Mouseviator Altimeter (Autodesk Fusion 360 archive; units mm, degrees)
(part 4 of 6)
sketch "Back Outline" plane through (0, 39, 0) normal (0, 1, 0) x axis (-1, 0, 0)
  line L1 (14.9023, 9.8465) -> (12.6303, 7.5745)
  line L2 (18.0511, 2.3887) -> (20.2056, 4.5432)
  line L3 (17.6976, 2.7423) -> (18.0511, 2.3887)
  line L4 (19.852, 4.8967) -> (17.6976, 2.7423)
  line L5 (12.9839, 7.2209) -> (15.2558, 9.4929)
  line L6 (12.6303, 7.5745) -> (12.9839, 7.2209)
  line L7 (-2.5507, -17.506) -> (-4.8967, -19.852)
  line L8 (-2.1971, -17.8596) -> (-2.5507, -17.506)
  line L9 (-4.5432, -20.2056) -> (-2.1971, -17.8596)
  line L10 (-7.6598, -12.7156) -> (-9.8465, -14.9023)
  line L11 (-7.3063, -13.0692) -> (-7.6598, -12.7156)
  line L12 (-9.4929, -15.2558) -> (-7.3063, -13.0692)
  line L13 (-41.4655, -13.9983) -> (-36.1766, -13.9983)
  line L14 (-41.4655, -20.5361) -> (-41.4655, -13.9983)
  line L15 (-36.4994, -34.1766) -> (-41.1157, -22.3885)
  line L16 (-23.2139, -41.1177) -> (-33.6166, -37.0564)
  curve K1 (-21.3665, -41.4655) -> (-21.9088, -41.4365)
  line L17 (28.9018, -41.4655) -> (-21.3665, -41.4655)
  line L18 (41.4655, 20.5361) -> (41.4655, -28.9018)
  curve K2 (41.4365, 21.0784) -> (41.4655, 20.5361)
  line L19 (36.4994, 34.1766) -> (41.1157, 22.3885)
  line L20 (26.5185, 40.8706) -> (34.1546, 36.8093)
  line L21 (14.9161, 41.4655) -> (24.1331, 41.4655)
  line L22 (14.9161, 35.8845) -> (14.9161, 41.4655)
  line L23 (-3.0839, 41.4655) -> (-3.0839, 35.8845)
  line L24 (-24.1231, 41.4655) -> (-3.0839, 41.4655)
  line L25 (-33.6166, 37.0564) -> (-26.5251, 40.8618)
  line L26 (-41.1157, 22.3885) -> (-36.4994, 34.1766)
  line L27 (-41.4655, 4.0017) -> (-41.4655, 20.5361)
  line L28 (-36.1766, 4.0017) -> (-41.4655, 4.0017)
  line L29 (0, -31.4655) -> (0, 0)
  line L30 (-3.75, -18.1203) -> (-3.75, -31.4655)
  line L31 (3.75, -31.4655) -> (3.75, -0.2296)
  line L32 (0, 0) -> (30.9023, -30.9023)
  line L33 (-2.6517, -2.6517) -> (28.2507, -33.554)
  line L34 (2.6517, 2.6517) -> (33.554, -28.2507)
  line L35 (30.3606, 27.5008) -> (31.4655, 19.6071)
  line L36 (-20.4401, -31.4655) -> (-27.6044, -29.4666)
  line L37 (-22.8865, 31.4655) -> (-17.677, 31.4655)
  line L38 (-27.8686, 28.7921) -> (-22.8865, 31.4655)
  line L39 (-31.4655, 19.6071) -> (-27.8686, 28.7921)
  line L40 (-31.4655, 18.6813) -> (-31.4655, 19.6071)
  line L41 (30.4699, 22.1494) -> (31.4655, 19.6071)
  line L42 (-20.4401, -31.4655) -> (-25.1073, -29.6434)
  line L43 (28.9018, -31.4655) -> (-20.4401, -31.4655)
  line L44 (31.4655, 19.6071) -> (31.4655, -28.9018)
  arc A1 centre (17.5539, 7.1948) radius 3.75 clockwise from (14.9023, 9.8465) to (20.2056, 4.5432)
  arc A2 centre (17.5539, 7.1948) radius 3.25 clockwise from (15.2558, 9.4929) to (19.852, 4.8967)
  arc A3 centre (-7.1948, -17.5539) radius 3.75 clockwise from (-4.5432, -20.2056) to (-9.8465, -14.9023)
  arc A4 centre (-7.1948, -17.5539) radius 3.25 clockwise from (-4.8967, -19.852) to (-9.4929, -15.2558)
  arc A5 centre (-36.3855, -20.5361) radius 5.08 clockwise from (-41.1157, -22.3885) to (-41.4655, -20.5361)
  arc A6 centre (-31.7692, -32.3242) radius 5.08 clockwise from (-33.6166, -37.0564) to (-36.4994, -34.1766)
  arc A7 centre (-21.3665, -36.3855) radius 5.08 clockwise from (-21.9088, -41.4365) to (-23.2139, -41.1177)
  arc A8 centre (28.9018, -28.9018) radius 12.5637 clockwise from (41.4655, -28.9018) to (28.9018, -41.4655)
  arc A9 centre (36.3855, 20.5361) radius 5.08 clockwise from (41.1157, 22.3885) to (41.4365, 21.0784)
  arc A10 centre (31.7692, 32.3242) radius 5.08 clockwise from (34.1546, 36.8093) to (36.4994, 34.1766)
  arc A11 centre (24.1331, 36.3855) radius 5.08 clockwise from (24.1331, 41.4655) to (26.5185, 40.8706)
  arc A12 centre (5.9161, 24.325) radius 14.65 clockwise from (14.9161, 35.8845) to (-3.0839, 35.8845)
  arc A13 centre (-24.1231, 36.3855) radius 5.08 clockwise from (-26.5251, 40.8618) to (-24.1231, 41.4655)
  arc A14 centre (-31.7692, 32.3242) radius 5.08 clockwise from (-36.4994, 34.1766) to (-33.6166, 37.0564)
  arc A15 centre (-36.3855, 20.5361) radius 5.08 clockwise from (-41.4655, 20.5361) to (-41.1157, 22.3885)
  arc A16 centre (-24.6171, -4.9983) radius 14.65 clockwise from (-36.1766, 4.0017) to (-36.1766, -13.9983)
  circle C1 centre (17.5539, 7.1948) radius 1.4
  circle C2 centre (-7.1948, -17.5539) radius 1.4
  circle C3 centre (30.9023, -30.9023) radius 5.5
  circle C4 centre (-18.76, 36.96) radius 1
  circle C5 centre (31.4309, 31.4309) radius 2.159
  circle C6 centre (-31.4309, -31.4309) radius 2.159
  circle C7 centre (-18.76, -36.96) radius 1
  circle C8 centre (18.76, 36.96) radius 1
  circle C9 centre (-31.4309, 31.4309) radius 2.159
  circle C10 centre (0, 0) radius 5
  circle C11 centre (-36.96, 18.76) radius 1
  circle C12 centre (36.96, 18.76) radius 1
  circle C13 centre (-36.96, -18.76) radius 1
  circle C14 centre (0, 0) radius 22.5
  circle C15 centre (30.9023, -30.9023) radius 15
  arc A17 centre (5.9161, 24.325) radius 24.65 clockwise from (-18.101, 18.7749) to (-17.677, 31.4655)
  arc A18 centre (-24.6171, -4.9983) radius 24.65 clockwise from (-31.4655, 18.6813) to (-18.101, 18.7749)
  arc A19 centre (5.9161, 24.325) radius 24.65 clockwise from (30.4699, 22.1494) to (-0.6001, 0.5519)
  arc A20 centre (-24.6171, -4.9983) radius 24.65 clockwise from (-0.6001, 0.5519) to (-25.1073, -29.6434)
  arc A21 centre (28.9018, -28.9018) radius 2.5637 clockwise from (31.4655, -28.9018) to (28.9018, -31.4655)
  point P1 (0, 0)
  point P86 (0, 0)
  point P87 (0, -31.4655)
  point P88 (-3.75, -31.4655)
  point P89 (-3.75, -18.1203)
  point P90 (3.75, -0.2296)
  point P91 (3.75, -31.4655)
  point P92 (0, 0)
  point P62 (30.9023, -30.9023)
  point P93 (30.9023, -30.9023)
  point P94 (0, 0)
  point P99 (30.9023, -30.9023)
  coincident P1 P86
  coincident P87 L43
  perpendicular L29 L43
  coincident P88 L43
  coincident P89 A20
  vertical L30
  coincident P90 A19
  coincident P91 L43
  perpendicular L31 L43
  coincident P1 P92
  coincident P62 P93
  coincident P1 P94
  coincident P93 P99
  dimension "d336" = -10
  dimension "d337" distance L29 L30 = 3.75 (= "( 7.5 / 2 ) * 1 mm")
  dimension "d338" distance L29 L31 = 3.75 (= "d337")
  dimension "d339" diameter C14 = 45
  dimension "d340" = -3.75 (= "( -7.5 / 2 ) * 1 mm")
  dimension "d341" = 3.75 (= "( 7.5 / 2 ) * 1 mm")
  dimension "d344" diameter C15 = 30
extrude "Extrude13" cut sketch "Back Outline" profile of A1 A19 L43 A20 L44 C14 L33 L34 C15 L35 L36 to an object
fillet "Fillet2" radius 1.5
sketch "Support Holes" plane through (0, 3.5, 0) normal (0, -1, 0) x axis (1, 0, 0)
  line L1 (32.6235, 7.6129) -> (25.3452, 5.7982)
  line L2 (25.3452, -5.7982) -> (32.6737, -7.3944)
  curve K1 (-41.4655, 20.5361) -> (-41.4365, 21.0784)
  line L3 (-41.4655, -28.9018) -> (-41.4655, 20.5361)
  line L4 (21.3665, -41.4655) -> (-28.9018, -41.4655)
  curve K2 (21.9088, -41.4365) -> (21.3665, -41.4655)
  line L5 (33.6166, -37.0564) -> (23.2139, -41.1177)
  line L6 (41.1157, -22.3885) -> (36.4994, -34.1766)
  line L7 (41.4655, 20.5361) -> (41.4655, -20.5361)
  line L8 (36.4994, 34.1766) -> (41.1157, 22.3885)
  line L9 (26.5251, 40.8618) -> (33.6166, 37.0564)
  line L10 (-24.1331, 41.4655) -> (24.1231, 41.4655)
  line L11 (-34.1546, 36.8093) -> (-26.5185, 40.8706)
  line L12 (-41.1157, 22.3885) -> (-36.4994, 34.1766)
  circle C1 centre (-30.9024, -30.9024) radius 3.25
  circle C2 centre (-0.2224, 0.034) radius 5.25
  circle C3 centre (18.76, 36.96) radius 1.4
  circle C4 centre (-36.96, 18.76) radius 1.4
  circle C5 centre (-18.76, 36.96) radius 1.4
  circle C6 centre (36.96, -18.76) radius 1.4
  circle C7 centre (31.4309, 31.4309) radius 2.159
  circle C8 centre (36.96, 18.76) radius 1.4
  circle C9 centre (18.76, -36.96) radius 1.4
  circle C10 centre (-31.4309, 31.4309) radius 2.159
  arc A1 centre (0, 0) radius 33.5 clockwise from (32.6235, 7.6129) to (32.6737, -7.3944)
  arc A2 centre (0, 0) radius 26 clockwise from (25.3452, 5.7982) to (25.3452, -5.7982)
  circle C11 centre (31.4309, -31.4309) radius 2.159
  arc A3 centre (-36.3855, 20.5361) radius 5.08 clockwise from (-41.4365, 21.0784) to (-41.1157, 22.3885)
  arc A4 centre (-28.9018, -28.9018) radius 12.5637 clockwise from (-28.9018, -41.4655) to (-41.4655, -28.9018)
  arc A5 centre (21.3665, -36.3855) radius 5.08 clockwise from (23.2139, -41.1177) to (21.9088, -41.4365)
  arc A6 centre (31.7692, -32.3242) radius 5.08 clockwise from (36.4994, -34.1766) to (33.6166, -37.0564)
  arc A7 centre (36.3855, -20.5361) radius 5.08 clockwise from (41.4655, -20.5361) to (41.1157, -22.3885)
  arc A8 centre (36.3855, 20.5361) radius 5.08 clockwise from (41.1157, 22.3885) to (41.4655, 20.5361)
  arc A9 centre (31.7692, 32.3242) radius 5.08 clockwise from (33.6166, 37.0564) to (36.4994, 34.1766)
  arc A10 centre (24.1231, 36.3855) radius 5.08 clockwise from (24.1231, 41.4655) to (26.5251, 40.8618)
  arc A11 centre (-24.1331, 36.3855) radius 5.08 clockwise from (-26.5185, 40.8706) to (-24.1331, 41.4655)
  arc A12 centre (-31.7692, 32.3242) radius 5.08 clockwise from (-36.4994, 34.1766) to (-34.1546, 36.8093)
  circle C12 centre (-17.3319, -36.9825) radius 1
  circle C13 centre (-37.3525, -16.6048) radius 1
extrude "Extrude6" cut sketch "Support Holes" profile of C12 C13 to an object
hole "Hole2" HoleDepth 4 HoleDiameter 5 TipAngle 180
extrude "Extrude3" cut sketch "Sketch1" to an object
decal "Decal2"
extrude "Extrude5" cut sketch "Sketch1" profile of A12 A14 L16 A17 A18 L20 to an object
work_plane "WorkPlane2" AlongDistance 0.75
sketch "Sketch1" plane through (0, 8.25, 0) normal (0, 1, 0) x axis (1, 0, 0)
  line L1 (38.0143, -15.1613) -> (35.9057, -22.3587)
  line L2 (19.7873, -9.8212) -> (38.0143, -15.1613)
  line L3 (17.6786, -17.0187) -> (19.7873, -9.8212)
  line L4 (35.9057, -22.3587) -> (17.6786, -17.0187)
  line L5 (23.336, -34.9394) -> (14.184, -38.9806)
  line L6 (15.0207, -16.1078) -> (23.336, -34.9394)
  line L7 (5.8687, -20.149) -> (15.0207, -16.1078)
  line L8 (14.184, -38.9806) -> (5.8687, -20.149)
  line L9 (22.1039, 35.2627) -> (15.4161, 38.6573)
  line L10 (16.8157, 24.8442) -> (22.1039, 35.2627)
  line L11 (10.1279, 28.2387) -> (16.8157, 24.8442)
  line L12 (15.4161, 38.6573) -> (10.1279, 28.2387)
  line L13 (35.2627, 22.1039) -> (38.6573, 15.4161)
  line L14 (24.8442, 16.8157) -> (35.2627, 22.1039)
  line L15 (28.2387, 10.1279) -> (24.8442, 16.8157)
  line L16 (38.6573, 15.4161) -> (28.2387, 10.1279)
  line L17 (-35.8292, 20.0315) -> (-38.8758, 13.1782)
  line L18 (-25.675, 15.5175) -> (-35.8292, 20.0315)
  line L19 (-28.7216, 8.6642) -> (-25.675, 15.5175)
  line L20 (-38.8758, 13.1782) -> (-28.7216, 8.6642)
  line L21 (-13.9363, 38.5738) -> (-20.7275, 35.3911)
  line L22 (-9.2354, 28.5431) -> (-13.9363, 38.5738)
  line L23 (-16.0266, 25.3604) -> (-9.2354, 28.5431)
  line L24 (-20.7275, 35.3911) -> (-16.0266, 25.3604)
  circle C1 centre (0, 0) radius 30
  circle C2 centre (36.96, 18.76) radius 3.75
  circle C3 centre (36.96, -18.76) radius 3.75
  circle C4 centre (18.76, 36.96) radius 3.75
  circle C5 centre (-37.3525, 16.6048) radius 3.75
  circle C6 centre (-17.3319, 36.9825) radius 3.75
  circle C7 centre (18.76, -36.96) radius 3.75
  point P1 (0, 0)
  point P2 (0, 0)
  point P3 (35.9057, -22.3587)
  point P4 (38.0143, -15.1613)
  point P18 (36.96, -18.76)
  point P19 (18.76, -36.96)
  point P39 (18.76, -36.96)
  point P16 (36.96, -18.76)
  point P15 (36.96, 18.76)
  point P20 (36.96, 18.76)
  point P21 (18.76, 36.96)
  point P14 (10.1279, 28.2387)
  point P13 (16.8157, 24.8442)
  point P12 (22.1039, 35.2627)
  point P17 (18.76, 36.96)
  point P25 (28.2387, 10.1279)
  point P24 (24.8442, 16.8157)
  point P22 (38.6573, 15.4161)
  point P23 (35.2627, 22.1039)
  point P26 (36.96, 18.76)
  point P30 (-35.8292, 20.0315)
  point P29 (-38.8758, 13.1782)
  point P34 (-13.9363, 38.5738)
  point P33 (-20.7275, 35.3911)
  point P37 (-17.3319, 36.9825)
  point P28 (-17.3319, 36.9825)
  point P35 (-9.2354, 28.5431)
  point P36 (-16.0266, 25.3604)
  point P38 (-37.3525, 16.6048)
  point P32 (-28.7216, 8.6642)
  point P31 (-25.675, 15.5175)
  point P27 (-37.3525, 16.6048)
  coincident P1 P2
  perpendicular L1 L2
  parallel L1 L3
  parallel L2 L4
  perpendicular L5 L6
  parallel L5 L7
  parallel L6 L8
  perpendicular L9 L10
  parallel L9 L11
  parallel L10 L12
  coincident P3 C3
  coincident P4 C3
  midpoint L1 P18
  midpoint L5 P19
  coincident P19 P39
  coincident P16 P18
  coincident P15 P20
  midpoint L9 P21
  coincident C1 P14
  coincident C1 P13
  coincident P12 C4
  coincident P17 P21
  perpendicular L13 L14
  parallel L13 L15
  parallel L14 L16
  coincident C1 P25
  coincident C1 P24
  coincident C2 P22
  coincident C2 P23
  midpoint L13 P26
  perpendicular L17 L18
  parallel L17 L19
  parallel L18 L20
  coincident C5 P30
  coincident C5 P29
  perpendicular L21 L22
  parallel L21 L23
  parallel L22 L24
  coincident C6 P34
  coincident C6 P33
  midpoint L21 P37
  coincident P28 P37
  coincident C1 P35
  coincident C1 P36
  midpoint L17 P38
  coincident C1 P32
  coincident C1 P31
  coincident P27 P38
  dimension "d270" diameter C1 = 60
extrude "Extrude1" new body sketch "Sketch1" profile of C1 C2 L14 L16 C6 L22 L24 along normal blind 5
chamfer "Chamfer1" distance 11 distance 4
fillet "Fillet1" radius 1.5 0.5
mirror "Mirror1" mirrorStitchTolerance 0.1
as_built_joint "As-built3" OffsetX 0 OffsetY 0 OffsetZ 0 AngleZ 0
as_built_joint "As-built5" OffsetX 0 OffsetY 0 OffsetZ 0 AngleZ 0 RotateRest -50
as_built_joint "As-built6"
as_built_joint "As-built7" OffsetX 0 OffsetY 0 OffsetZ 0 AngleZ 0
as_built_joint "As-built8" OffsetX 0 OffsetY 0 OffsetZ 0 AngleZ 0
motion_link "MotionLink1" Value1 360 Value2 -360
motion_link "MotionLink2" Value1 360 Value2 -360
sketch "D Shaft" plane through (0, 18.05, 0) normal (0, -1, 0) x axis (1, 0, 0)
  line L1 (-4.5346, -8.7261) -> (-4.7021, -8.8256)
  line L2 (-4.3651, -8.6158) -> (-4.5346, -8.7261)
  line L3 (-4.2116, -8.5065) -> (-4.3651, -8.6158)
  line L4 (-4.0743, -8.3999) -> (-4.2116, -8.5065)
  line L5 (-3.9541, -8.2982) -> (-4.0743, -8.3999)
  line L6 (-3.8486, -8.201) -> (-3.9541, -8.2982)
  line L7 (-3.7582, -8.1106) -> (-3.8486, -8.201)
  line L8 (-3.681, -8.0265) -> (-3.7582, -8.1106)
  line L9 (-3.6174, -7.9512) -> (-3.681, -8.0265)
  line L10 (-3.566, -7.8849) -> (-3.6174, -7.9512)
  line L11 (-3.4961, -7.7827) -> (-3.566, -7.8849)
  line L12 (-3.4639, -7.7262) -> (-3.4961, -7.7827)
  line L13 (-3.4053, -7.6041) -> (-3.4639, -7.7262)
  line L14 (-3.3474, -7.5073) -> (-3.4053, -7.6041)
  line L15 (-3.288, -7.4286) -> (-3.3474, -7.5073)
  line L16 (-3.2286, -7.3679) -> (-3.288, -7.4286)
  line L17 (-3.1993, -7.3443) -> (-3.2286, -7.3679)
  line L18 (-3.1705, -7.3251) -> (-3.1993, -7.3443)
  line L19 (-3.1424, -7.3103) -> (-3.1705, -7.3251)
  line L20 (-3.1151, -7.2999) -> (-3.1424, -7.3103)
  line L21 (-3.0889, -7.2938) -> (-3.1151, -7.2999)
  line L22 (-3.0638, -7.292) -> (-3.0889, -7.2938)
  line L23 (-3.0401, -7.2944) -> (-3.0638, -7.292)
  line L24 (-3.0179, -7.301) -> (-3.0401, -7.2944)
  line L25 (-2.8761, -7.358) -> (-3.0179, -7.301)
  line L26 (-2.702, -7.4237) -> (-2.8761, -7.358)
  line L27 (-2.5264, -7.4853) -> (-2.702, -7.4237)
  line L28 (-2.3811, -7.5327) -> (-2.5264, -7.4853)
  line L29 (-2.3599, -7.542) -> (-2.3811, -7.5327)
  line L30 (-2.3402, -7.5554) -> (-2.3599, -7.542)
  line L31 (-2.3221, -7.5729) -> (-2.3402, -7.5554)
  line L32 (-2.306, -7.5944) -> (-2.3221, -7.5729)
  line L33 (-2.2918, -7.6199) -> (-2.306, -7.5944)
  line L34 (-2.2797, -7.6493) -> (-2.2918, -7.6199)
  line L35 (-2.27, -7.6825) -> (-2.2797, -7.6493)
  line L36 (-2.2627, -7.7195) -> (-2.27, -7.6825)
  line L37 (-2.2562, -7.8041) -> (-2.2627, -7.7195)
  line L38 (-2.2613, -7.9026) -> (-2.2562, -7.8041)
  line L39 (-2.2792, -8.014) -> (-2.2613, -7.9026)
  line L40 (-2.3128, -8.1452) -> (-2.2792, -8.014)
  line L41 (-2.3244, -8.2092) -> (-2.3128, -8.1452)
  line L42 (-2.3366, -8.3324) -> (-2.3244, -8.2092)
  line L43 (-2.3398, -8.4162) -> (-2.3366, -8.3324)
  line L44 (-2.3395, -8.5148) -> (-2.3398, -8.4162)
  line L45 (-2.3344, -8.6288) -> (-2.3395, -8.5148)
  line L46 (-2.3233, -8.7562) -> (-2.3344, -8.6288)
  line L47 (-2.3049, -8.8985) -> (-2.3233, -8.7562)
  line L48 (-2.2782, -9.0536) -> (-2.3049, -8.8985)
  line L49 (-2.2416, -9.2235) -> (-2.2782, -9.0536)
  line L50 (-2.1943, -9.4059) -> (-2.2416, -9.2235)
  line L51 (-2.1353, -9.5994) -> (-2.1943, -9.4059)
  line L52 (-2.071, -9.7833) -> (-2.1353, -9.5994)
  line L53 (-1.2767, -9.7508) -> (-1.4, -9.9016)
  line L54 (-1.1551, -9.5891) -> (-1.2767, -9.7508)
  line L55 (-1.0482, -9.434) -> (-1.1551, -9.5891)
  line L56 (-0.9557, -9.2868) -> (-1.0482, -9.434)
  line L57 (-0.8776, -9.1501) -> (-0.9557, -9.2868)
  line L58 (-0.8117, -9.0228) -> (-0.8776, -9.1501)
  line L59 (-0.7577, -8.9068) -> (-0.8117, -9.0228)
  line L60 (-0.7138, -8.8015) -> (-0.7577, -8.9068)
  line L61 (-0.6798, -8.7089) -> (-0.7138, -8.8015)
  line L62 (-0.6542, -8.6291) -> (-0.6798, -8.7089)
  line L63 (-0.6235, -8.5091) -> (-0.6542, -8.6291)
  line L64 (-0.6125, -8.445) -> (-0.6235, -8.5091)
  line L65 (-0.5992, -8.3102) -> (-0.6125, -8.445)
  line L66 (-0.5779, -8.1994) -> (-0.5992, -8.3102)
  line L67 (-0.549, -8.1052) -> (-0.5779, -8.1994)
  line L68 (-0.5139, -8.0278) -> (-0.549, -8.1052)
  line L69 (-0.4945, -7.9956) -> (-0.5139, -8.0278)
  line L70 (-0.474, -7.9677) -> (-0.4945, -7.9956)
  line L71 (-0.4526, -7.9442) -> (-0.474, -7.9677)
  line L72 (-0.4306, -7.9251) -> (-0.4526, -7.9442)
  line L73 (-0.408, -7.9104) -> (-0.4306, -7.9251)
  line L74 (-0.3851, -7.9001) -> (-0.408, -7.9104)
  line L75 (-0.362, -7.8943) -> (-0.3851, -7.9001)
  line L76 (-0.3389, -7.8928) -> (-0.362, -7.8943)
  line L77 (-0.1861, -7.8979) -> (-0.3389, -7.8928)
  line L78 (0, -7.9001) -> (-0.1861, -7.8979)
  line L79 (0.186, -7.8979) -> (0, -7.9001)
  line L80 (0.3388, -7.8928) -> (0.186, -7.8979)
  line L81 (0.3619, -7.8943) -> (0.3388, -7.8928)
  line L82 (0.385, -7.9001) -> (0.3619, -7.8943)
  line L83 (0.4079, -7.9104) -> (0.385, -7.9001)
  line L84 (0.4305, -7.9251) -> (0.4079, -7.9104)
  line L85 (0.4526, -7.9442) -> (0.4305, -7.9251)
  line L86 (0.4739, -7.9677) -> (0.4526, -7.9442)
  line L87 (0.4944, -7.9956) -> (0.4739, -7.9677)
  line L88 (0.5139, -8.0278) -> (0.4944, -7.9956)
  line L89 (0.549, -8.1052) -> (0.5139, -8.0278)
  line L90 (0.5779, -8.1994) -> (0.549, -8.1052)
  line L91 (0.5991, -8.3102) -> (0.5779, -8.1994)
  line L92 (0.6124, -8.445) -> (0.5991, -8.3102)
  line L93 (0.6234, -8.5091) -> (0.6124, -8.445)
  line L94 (0.6541, -8.6291) -> (0.6234, -8.5091)
  line L95 (0.6798, -8.7089) -> (0.6541, -8.6291)
  line L96 (0.7138, -8.8015) -> (0.6798, -8.7089)
  line L97 (0.7576, -8.9068) -> (0.7138, -8.8015)
  line L98 (0.8116, -9.0228) -> (0.7576, -8.9068)
  line L99 (0.8775, -9.1501) -> (0.8116, -9.0228)
  line L100 (0.9556, -9.2868) -> (0.8775, -9.1501)
  line L101 (1.0481, -9.434) -> (0.9556, -9.2868)
  line L102 (1.155, -9.5891) -> (1.0481, -9.434)
  line L103 (1.2767, -9.7508) -> (1.155, -9.5891)
  line L104 (1.4, -9.9016) -> (1.2767, -9.7508)
  line L105 (2.1352, -9.5994) -> (2.0709, -9.7833)
  line L106 (2.1942, -9.4059) -> (2.1352, -9.5994)
  line L107 (2.2416, -9.2235) -> (2.1942, -9.4059)
  line L108 (2.2782, -9.0536) -> (2.2416, -9.2235)
  line L109 (2.3049, -8.8985) -> (2.2782, -9.0536)
  line L110 (2.3232, -8.7562) -> (2.3049, -8.8985)
  line L111 (2.3343, -8.6288) -> (2.3232, -8.7562)
  line L112 (2.3394, -8.5148) -> (2.3343, -8.6288)
  line L113 (2.3398, -8.4162) -> (2.3394, -8.5148)
  line L114 (2.3365, -8.3324) -> (2.3398, -8.4162)
  line L115 (2.3244, -8.2092) -> (2.3365, -8.3324)
  line L116 (2.3128, -8.1452) -> (2.3244, -8.2092)
  line L117 (2.2792, -8.014) -> (2.3128, -8.1452)
  line L118 (2.2613, -7.9026) -> (2.2792, -8.014)
  line L119 (2.2562, -7.8041) -> (2.2613, -7.9026)
  line L120 (2.2627, -7.7195) -> (2.2562, -7.8041)
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  point P975 (-9.344, 9.9736)
  point P977 (-9.344, 9.9736)
  point P976 (-12.2851, 5.9884)
  point P978 (-12.2851, 5.9884)
  coincident P975 P977
  coincident P976 P978
  dimension "d422" distance = 0.2 (= "DShaftToll")
  dimension "d423" diameter = 5.4
  dimension "d424" distance = 3.2 (= "d423 / 2 + 0.5 mm")
extrude "Extrude5" cut sketch "D Shaft" to an object
extrude "Extrude6" add sketch "D Shaft" to an object
sketch "1K Text" plane through (0, 18.05, 0) normal (0, -1, 0) x axis (1, 0, 0)
  line L1 (-4.5346, -8.7261) -> (-4.7021, -8.8256)
  line L2 (-4.3651, -8.6158) -> (-4.5346, -8.7261)
  line L3 (-4.2116, -8.5065) -> (-4.3651, -8.6158)
  line L4 (-4.0743, -8.3999) -> (-4.2116, -8.5065)
  line L5 (-3.9541, -8.2982) -> (-4.0743, -8.3999)
  line L6 (-3.8486, -8.201) -> (-3.9541, -8.2982)
  line L7 (-3.7582, -8.1106) -> (-3.8486, -8.201)
  line L8 (-3.681, -8.0265) -> (-3.7582, -8.1106)
  line L9 (-3.6174, -7.9512) -> (-3.681, -8.0265)
  line L10 (-3.566, -7.8849) -> (-3.6174, -7.9512)
  line L11 (-3.4961, -7.7827) -> (-3.566, -7.8849)
  line L12 (-3.4639, -7.7262) -> (-3.4961, -7.7827)
  line L13 (-3.4053, -7.6041) -> (-3.4639, -7.7262)
  line L14 (-3.3474, -7.5073) -> (-3.4053, -7.6041)
  line L15 (-3.288, -7.4286) -> (-3.3474, -7.5073)
  line L16 (-3.2286, -7.3679) -> (-3.288, -7.4286)
  line L17 (-3.1993, -7.3443) -> (-3.2286, -7.3679)
  line L18 (-3.1705, -7.3251) -> (-3.1993, -7.3443)
  line L19 (-3.1424, -7.3103) -> (-3.1705, -7.3251)
  line L20 (-3.1151, -7.2999) -> (-3.1424, -7.3103)
  line L21 (-3.0889, -7.2938) -> (-3.1151, -7.2999)
  line L22 (-3.0638, -7.292) -> (-3.0889, -7.2938)
  line L23 (-3.0401, -7.2944) -> (-3.0638, -7.292)
  line L24 (-3.0179, -7.301) -> (-3.0401, -7.2944)
  line L25 (-2.8761, -7.358) -> (-3.0179, -7.301)
  line L26 (-2.702, -7.4237) -> (-2.8761, -7.358)
  line L27 (-2.5264, -7.4853) -> (-2.702, -7.4237)
  line L28 (-2.3811, -7.5327) -> (-2.5264, -7.4853)
  line L29 (-2.3599, -7.542) -> (-2.3811, -7.5327)
  line L30 (-2.3402, -7.5554) -> (-2.3599, -7.542)
  line L31 (-2.3221, -7.5729) -> (-2.3402, -7.5554)
  line L32 (-2.306, -7.5944) -> (-2.3221, -7.5729)
  line L33 (-2.2918, -7.6199) -> (-2.306, -7.5944)
  line L34 (-2.2797, -7.6493) -> (-2.2918, -7.6199)
  line L35 (-2.27, -7.6825) -> (-2.2797, -7.6493)
  line L36 (-2.2627, -7.7195) -> (-2.27, -7.6825)
  line L37 (-2.2562, -7.8041) -> (-2.2627, -7.7195)
  line L38 (-2.2613, -7.9026) -> (-2.2562, -7.8041)
  line L39 (-2.2792, -8.014) -> (-2.2613, -7.9026)
  line L40 (-2.3128, -8.1452) -> (-2.2792, -8.014)
  line L41 (-2.3244, -8.2092) -> (-2.3128, -8.1452)
  line L42 (-2.3366, -8.3324) -> (-2.3244, -8.2092)
  line L43 (-2.3398, -8.4162) -> (-2.3366, -8.3324)
  line L44 (-2.3395, -8.5148) -> (-2.3398, -8.4162)
  line L45 (-2.3344, -8.6288) -> (-2.3395, -8.5148)
  line L46 (-2.3233, -8.7562) -> (-2.3344, -8.6288)
  line L47 (-2.3049, -8.8985) -> (-2.3233, -8.7562)
  line L48 (-2.2782, -9.0536) -> (-2.3049, -8.8985)
  line L49 (-2.2416, -9.2235) -> (-2.2782, -9.0536)
  line L50 (-2.1943, -9.4059) -> (-2.2416, -9.2235)
  line L51 (-2.1353, -9.5994) -> (-2.1943, -9.4059)
  line L52 (-2.071, -9.7833) -> (-2.1353, -9.5994)
  line L53 (-1.2767, -9.7508) -> (-1.4, -9.9016)
  line L54 (-1.1551, -9.5891) -> (-1.2767, -9.7508)
  line L55 (-1.0482, -9.434) -> (-1.1551, -9.5891)
  line L56 (-0.9557, -9.2868) -> (-1.0482, -9.434)
  line L57 (-0.8776, -9.1501) -> (-0.9557, -9.2868)
  line L58 (-0.8117, -9.0228) -> (-0.8776, -9.1501)
  line L59 (-0.7577, -8.9068) -> (-0.8117, -9.0228)
  line L60 (-0.7138, -8.8015) -> (-0.7577, -8.9068)
  line L61 (-0.6798, -8.7089) -> (-0.7138, -8.8015)
  line L62 (-0.6542, -8.6291) -> (-0.6798, -8.7089)
  line L63 (-0.6235, -8.5091) -> (-0.6542, -8.6291)
  line L64 (-0.6125, -8.445) -> (-0.6235, -8.5091)
  line L65 (-0.5992, -8.3102) -> (-0.6125, -8.445)
  line L66 (-0.5779, -8.1994) -> (-0.5992, -8.3102)
  line L67 (-0.549, -8.1052) -> (-0.5779, -8.1994)
  line L68 (-0.5139, -8.0278) -> (-0.549, -8.1052)
  line L69 (-0.4945, -7.9956) -> (-0.5139, -8.0278)
  line L70 (-0.474, -7.9677) -> (-0.4945, -7.9956)
  line L71 (-0.4526, -7.9442) -> (-0.474, -7.9677)
  line L72 (-0.4306, -7.9251) -> (-0.4526, -7.9442)
  line L73 (-0.408, -7.9104) -> (-0.4306, -7.9251)
  line L74 (-0.3851, -7.9001) -> (-0.408, -7.9104)
  line L75 (-0.362, -7.8943) -> (-0.3851, -7.9001)
  line L76 (-0.3389, -7.8928) -> (-0.362, -7.8943)
  line L77 (-0.1861, -7.8979) -> (-0.3389, -7.8928)
  line L78 (0, -7.9001) -> (-0.1861, -7.8979)
  line L79 (0.186, -7.8979) -> (0, -7.9001)
  line L80 (0.3388, -7.8928) -> (0.186, -7.8979)
  line L81 (0.3619, -7.8943) -> (0.3388, -7.8928)
  line L82 (0.385, -7.9001) -> (0.3619, -7.8943)
  line L83 (0.4079, -7.9104) -> (0.385, -7.9001)
  line L84 (0.4305, -7.9251) -> (0.4079, -7.9104)
  line L85 (0.4526, -7.9442) -> (0.4305, -7.9251)
  line L86 (0.4739, -7.9677) -> (0.4526, -7.9442)
  line L87 (0.4944, -7.9956) -> (0.4739, -7.9677)
  line L88 (0.5139, -8.0278) -> (0.4944, -7.9956)
  line L89 (0.549, -8.1052) -> (0.5139, -8.0278)
  line L90 (0.5779, -8.1994) -> (0.549, -8.1052)
  line L91 (0.5991, -8.3102) -> (0.5779, -8.1994)
  line L92 (0.6124, -8.445) -> (0.5991, -8.3102)
  line L93 (0.6234, -8.5091) -> (0.6124, -8.445)
  line L94 (0.6541, -8.6291) -> (0.6234, -8.5091)
  line L95 (0.6798, -8.7089) -> (0.6541, -8.6291)
  line L96 (0.7138, -8.8015) -> (0.6798, -8.7089)
  line L97 (0.7576, -8.9068) -> (0.7138, -8.8015)
  line L98 (0.8116, -9.0228) -> (0.7576, -8.9068)
  line L99 (0.8775, -9.1501) -> (0.8116, -9.0228)
  line L100 (0.9556, -9.2868) -> (0.8775, -9.1501)
  line L101 (1.0481, -9.434) -> (0.9556, -9.2868)
  line L102 (1.155, -9.5891) -> (1.0481, -9.434)
  line L103 (1.2767, -9.7508) -> (1.155, -9.5891)
  line L104 (1.4, -9.9016) -> (1.2767, -9.7508)
  line L105 (2.1352, -9.5994) -> (2.0709, -9.7833)
  line L106 (2.1942, -9.4059) -> (2.1352, -9.5994)
  line L107 (2.2416, -9.2235) -> (2.1942, -9.4059)
  line L108 (2.2782, -9.0536) -> (2.2416, -9.2235)
  line L109 (2.3049, -8.8985) -> (2.2782, -9.0536)
  line L110 (2.3232, -8.7562) -> (2.3049, -8.8985)
  line L111 (2.3343, -8.6288) -> (2.3232, -8.7562)
  line L112 (2.3394, -8.5148) -> (2.3343, -8.6288)
  line L113 (2.3398, -8.4162) -> (2.3394, -8.5148)
  line L114 (2.3365, -8.3324) -> (2.3398, -8.4162)
  line L115 (2.3244, -8.2092) -> (2.3365, -8.3324)
  line L116 (2.3128, -8.1452) -> (2.3244, -8.2092)
  line L117 (2.2792, -8.014) -> (2.3128, -8.1452)
  line L118 (2.2613, -7.9026) -> (2.2792, -8.014)
  line L119 (2.2562, -7.8041) -> (2.2613, -7.9026)
  line L120 (2.2627, -7.7195) -> (2.2562, -7.8041)
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  dimension "d379" Text1-Height = 3
extrude "Extrude4" cut sketch "1K Text" against normal blind 1
sketch "D Shaft" plane through (0, 10.05, 0) normal (0, -1, 0) x axis (1, 0, 0)
  line L1 (-5.2896, -8.2901) -> (-5.2789, -8.0881)
  line L2 (-5.2921, -8.4849) -> (-5.2896, -8.2901)
  line L3 (-4.5346, -8.726) -> (-4.7021, -8.8255)
  line L4 (-4.3651, -8.6157) -> (-4.5346, -8.726)
  line L5 (-4.2115, -8.5064) -> (-4.3651, -8.6157)
  line L6 (-4.0743, -8.3998) -> (-4.2115, -8.5064)
  line L7 (-3.9541, -8.2981) -> (-4.0743, -8.3998)
  line L8 (-3.8486, -8.2009) -> (-3.9541, -8.2981)
  line L9 (-3.7582, -8.1105) -> (-3.8486, -8.2009)
  line L10 (-3.681, -8.0264) -> (-3.7582, -8.1105)
  line L11 (-3.6174, -7.9511) -> (-3.681, -8.0264)
  line L12 (-3.566, -7.8848) -> (-3.6174, -7.9511)
  line L13 (-3.4961, -7.7826) -> (-3.566, -7.8848)
  line L14 (-3.4639, -7.7261) -> (-3.4961, -7.7826)
  line L15 (-3.4053, -7.604) -> (-3.4639, -7.7261)
  line L16 (-3.3474, -7.5072) -> (-3.4053, -7.604)
  line L17 (-3.288, -7.4285) -> (-3.3474, -7.5072)
  line L18 (-3.2286, -7.3678) -> (-3.288, -7.4285)
  line L19 (-3.1993, -7.3442) -> (-3.2286, -7.3678)
  line L20 (-3.1705, -7.325) -> (-3.1993, -7.3442)
  line L21 (-3.1423, -7.3102) -> (-3.1705, -7.325)
  line L22 (-3.1151, -7.2998) -> (-3.1423, -7.3102)
  line L23 (-3.0888, -7.2937) -> (-3.1151, -7.2998)
  line L24 (-3.0638, -7.2919) -> (-3.0888, -7.2937)
  line L25 (-3.0401, -7.2943) -> (-3.0638, -7.2919)
  line L26 (-3.0179, -7.3008) -> (-3.0401, -7.2943)
  line L27 (-2.876, -7.3579) -> (-3.0179, -7.3008)
  line L28 (-2.702, -7.4236) -> (-2.876, -7.3579)
  line L29 (-2.5264, -7.4852) -> (-2.702, -7.4236)
  line L30 (-2.3811, -7.5326) -> (-2.5264, -7.4852)
  line L31 (-2.3598, -7.5419) -> (-2.3811, -7.5326)
  line L32 (-2.3401, -7.5553) -> (-2.3598, -7.5419)
  line L33 (-2.3221, -7.5728) -> (-2.3401, -7.5553)
  line L34 (-2.3059, -7.5943) -> (-2.3221, -7.5728)
  line L35 (-2.2917, -7.6198) -> (-2.3059, -7.5943)
  line L36 (-2.2797, -7.6492) -> (-2.2917, -7.6198)
  line L37 (-2.27, -7.6824) -> (-2.2797, -7.6492)
  line L38 (-2.2627, -7.7194) -> (-2.27, -7.6824)
  line L39 (-2.2562, -7.804) -> (-2.2627, -7.7194)
  line L40 (-2.2613, -7.9025) -> (-2.2562, -7.804)
  line L41 (-2.2792, -8.0138) -> (-2.2613, -7.9025)
  line L42 (-2.3128, -8.1451) -> (-2.2792, -8.0138)
  line L43 (-2.3244, -8.209) -> (-2.3128, -8.1451)
  line L44 (-2.3366, -8.3323) -> (-2.3244, -8.209)
  line L45 (-2.3398, -8.4161) -> (-2.3366, -8.3323)
  line L46 (-2.3395, -8.5147) -> (-2.3398, -8.4161)
  line L47 (-2.3343, -8.6287) -> (-2.3395, -8.5147)
  line L48 (-2.3233, -8.7561) -> (-2.3343, -8.6287)
  line L49 (-2.3049, -8.8984) -> (-2.3233, -8.7561)
  line L50 (-2.2782, -9.0535) -> (-2.3049, -8.8984)
  line L51 (-2.2416, -9.2234) -> (-2.2782, -9.0535)
  line L52 (-2.1942, -9.4058) -> (-2.2416, -9.2234)
  line L53 (-2.1352, -9.5993) -> (-2.1942, -9.4058)
  line L54 (-2.0709, -9.7832) -> (-2.1352, -9.5993)
  line L55 (-1.2767, -9.7507) -> (-1.4, -9.9015)
  line L56 (-1.1551, -9.589) -> (-1.2767, -9.7507)
  line L57 (-1.0482, -9.4339) -> (-1.1551, -9.589)
  line L58 (-0.9557, -9.2867) -> (-1.0482, -9.4339)
  line L59 (-0.8775, -9.15) -> (-0.9557, -9.2867)
  line L60 (-0.8116, -9.0227) -> (-0.8775, -9.15)
  line L61 (-0.7576, -8.9067) -> (-0.8116, -9.0227)
  line L62 (-0.7138, -8.8014) -> (-0.7576, -8.9067)
  line L63 (-0.6798, -8.7088) -> (-0.7138, -8.8014)
  line L64 (-0.6542, -8.629) -> (-0.6798, -8.7088)
  line L65 (-0.6234, -8.509) -> (-0.6542, -8.629)
  line L66 (-0.6125, -8.4449) -> (-0.6234, -8.509)
  line L67 (-0.5992, -8.3101) -> (-0.6125, -8.4449)
  line L68 (-0.5779, -8.1993) -> (-0.5992, -8.3101)
  line L69 (-0.549, -8.1051) -> (-0.5779, -8.1993)
  line L70 (-0.5139, -8.0277) -> (-0.549, -8.1051)
  line L71 (-0.4945, -7.9955) -> (-0.5139, -8.0277)
  line L72 (-0.474, -7.9676) -> (-0.4945, -7.9955)
  line L73 (-0.4526, -7.9441) -> (-0.474, -7.9676)
  line L74 (-0.4305, -7.925) -> (-0.4526, -7.9441)
  line L75 (-0.408, -7.9103) -> (-0.4305, -7.925)
  line L76 (-0.385, -7.9) -> (-0.408, -7.9103)
  line L77 (-0.3619, -7.8941) -> (-0.385, -7.9)
  line L78 (-0.3389, -7.8927) -> (-0.3619, -7.8941)
  line L79 (-0.186, -7.8978) -> (-0.3389, -7.8927)
  line L80 (0, -7.9) -> (-0.186, -7.8978)
  line L81 (0.186, -7.8978) -> (0, -7.9)
  line L82 (0.3389, -7.8927) -> (0.186, -7.8978)
  line L83 (0.3619, -7.8941) -> (0.3389, -7.8927)
  line L84 (0.385, -7.9) -> (0.3619, -7.8941)
  line L85 (0.408, -7.9103) -> (0.385, -7.9)
  line L86 (0.4305, -7.925) -> (0.408, -7.9103)
  line L87 (0.4526, -7.9441) -> (0.4305, -7.925)
  line L88 (0.474, -7.9676) -> (0.4526, -7.9441)
  line L89 (0.4945, -7.9955) -> (0.474, -7.9676)
  line L90 (0.5139, -8.0277) -> (0.4945, -7.9955)
  line L91 (0.549, -8.1051) -> (0.5139, -8.0277)
  line L92 (0.5779, -8.1993) -> (0.549, -8.1051)
  line L93 (0.5992, -8.3101) -> (0.5779, -8.1993)
  line L94 (0.6125, -8.4449) -> (0.5992, -8.3101)
  line L95 (0.6235, -8.509) -> (0.6125, -8.4449)
  line L96 (0.6542, -8.629) -> (0.6235, -8.509)
  line L97 (0.6798, -8.7088) -> (0.6542, -8.629)
  line L98 (0.7138, -8.8014) -> (0.6798, -8.7088)
  line L99 (0.7576, -8.9067) -> (0.7138, -8.8014)
  line L100 (0.8116, -9.0227) -> (0.7576, -8.9067)
  line L101 (0.8775, -9.15) -> (0.8116, -9.0227)
  line L102 (0.9557, -9.2867) -> (0.8775, -9.15)
  line L103 (1.0482, -9.4339) -> (0.9557, -9.2867)
  line L104 (1.1551, -9.589) -> (1.0482, -9.4339)
  line L105 (1.2767, -9.7507) -> (1.1551, -9.589)
  line L106 (1.4, -9.9015) -> (1.2767, -9.7507)
  line L107 (2.1352, -9.5993) -> (2.0709, -9.7832)
  line L108 (2.1942, -9.4058) -> (2.1352, -9.5993)
  line L109 (2.2416, -9.2234) -> (2.1942, -9.4058)
  line L110 (2.2782, -9.0535) -> (2.2416, -9.2234)
  line L111 (2.3049, -8.8984) -> (2.2782, -9.0535)
  line L112 (2.3233, -8.7561) -> (2.3049, -8.8984)
  line L113 (2.3343, -8.6287) -> (2.3233, -8.7561)
  line L114 (2.3395, -8.5147) -> (2.3343, -8.6287)
  line L115 (2.3398, -8.4161) -> (2.3395, -8.5147)
  line L116 (2.3366, -8.3323) -> (2.3398, -8.4161)
  line L117 (2.3244, -8.209) -> (2.3366, -8.3323)
  line L118 (2.3128, -8.1451) -> (2.3244, -8.209)
  line L119 (2.2792, -8.0138) -> (2.3128, -8.1451)
  line L120 (2.2613, -7.9025) -> (2.2792, -8.0138)
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  point P1004 (0.195, 16.4988)
  point P1005 (0.195, 16.4988)
  point P1003 (-3.7809, 16.061)
  point P1006 (-3.7809, 16.061)
  coincident P1004 P1005
  coincident P1003 P1006
  dimension "d415" distance = 0.2 (= "DShaftToll")
  dimension "d416" distance = 4.5 (= "d417 / 2 + 0.5 mm")
  dimension "d417" diameter = 8
extrude "Extrude8" cut sketch "D Shaft" to an object
extrude "Extrude9" add sketch "D Shaft" to an object
chamfer "Chamfer1" distance 0.5
copy_paste_bodies "CopyPasteBodies1"
component_from_bodies "Body->Comp2"
component_from_bodies "Body->Comp3"
component_from_bodies "Body->Comp1"
sketch "Sketch1" plane through (0, 2, 0) normal (0, -1, 0) x axis (1, 0, 0)
  line L1 (5.7809, -15.4542) -> (2.6381, -7.2245)
  line L2 (-2.1183, 19.2337) -> (0.195, 16.4988)
  line L3 (-3.7809, 16.061) -> (-2.1183, 19.2337)
  line L4 (-1.0026, -7.6255) -> (-2.2791, -16.3418)
  line L5 (-2.1183, 19.2337) -> (0, 0)
  line L6 (0.1414, 4.4258) -> (-3.1354, 34.1785)
  line L7 (-1.1173, 4.4359) -> (0.1414, 4.4258)
  line L8 (-4.3779, 34.0416) -> (-1.1173, 4.4359)
  line L9 (0.1414, 4.4258) -> (-4.3779, 34.0416)
  line L10 (-6.1952, 36.517) -> (-1.9003, 36.99)
  line L11 (-3.6381, 33.034) -> (-6.1952, 36.517)
  line L12 (-1.9003, 36.99) -> (-3.6381, 33.034)
  line L13 (0, 0) -> (-3.9112, 35.5137)
  line L14 (-3.1354, 34.1785) -> (-4.3779, 34.0416)
  circle C1 centre (0, 0) radius 4
  arc A1 centre (-0.1807, -0.3465) radius 7.3252 clockwise from (0.8371, -7.6007) to (-1.0026, -7.6255)
  arc A2 centre (0.2518, -0.2989) radius 7.3252 clockwise from (2.6381, -7.2245) to (0.8371, -7.6007)
  arc A3 centre (0, 0) radius 16.5 clockwise from (0.195, 16.4988) to (5.7809, -15.4542)
  arc A4 centre (0, 0) radius 16.5 clockwise from (-2.2791, -16.3418) to (-3.7809, 16.061)
  point P1 (0, 0)
  point P13 (0, 0)
  point P10 (-2.1183, 19.2337)
  point P14 (-2.1183, 19.2337)
  point P19 (-2.1183, 19.2337)
  point P23 (-3.9112, 35.5137)
  point P24 (-3.9112, 35.5137)
  point P25 (-4.3779, 34.0416)
  point P15 (-4.3779, 34.0416)
  point P26 (-3.1354, 34.1785)
  point P16 (-3.1354, 34.1785)
  coincident P1 P13
  coincident P10 P14
  parallel L6 L8
  parallel L5 L6
  midpoint L9 P19
  coincident P10 P19
  coincident P23 P24
  coincident L11 P25
  coincident P15 P25
  coincident L12 P26
  coincident P16 P26
  perpendicular L6 L14
  dimension "d384" distance P15 P16 = 1.25
extrude "Extrude1" add sketch "Sketch1" profile of L2 L3 L6 L8 L10 L11 L12 to an object
sketch "Sketch1" plane through (0, 3.5, 0) normal (0, -1, 0) x axis (1, 0, 0)
  line L1 (32.6235, 7.6129) -> (25.3452, 5.7982)
  line L2 (25.3452, -5.7982) -> (32.6737, -7.3944)
  curve K1 (-41.4655, 20.5361) -> (-41.4365, 21.0784)
  line L3 (-41.4655, -28.9018) -> (-41.4655, 20.5361)
  line L4 (21.3665, -41.4655) -> (-28.9018, -41.4655)
  curve K2 (21.9088, -41.4365) -> (21.3665, -41.4655)
  line L5 (33.6166, -37.0564) -> (23.2139, -41.1177)
  line L6 (41.1157, -22.3885) -> (36.4994, -34.1766)
  line L7 (41.4655, 20.5361) -> (41.4655, -20.5361)
  line L8 (36.4994, 34.1766) -> (41.1157, 22.3885)
  line L9 (26.5251, 40.8618) -> (33.6166, 37.0564)
  line L10 (-24.1331, 41.4655) -> (24.1231, 41.4655)
  line L11 (-34.1546, 36.8093) -> (-26.5185, 40.8706)
  line L12 (-41.1157, 22.3885) -> (-36.4994, 34.1766)
  circle C1 centre (-17.3319, -36.9825) radius 1
  circle C2 centre (-37.3525, -16.6048) radius 1
  circle C3 centre (-30.9024, -30.9024) radius 3.25
  circle C4 centre (36.96, -18.76) radius 1.4
  arc A1 centre (0, 0) radius 33.5 clockwise from (32.6235, 7.6129) to (32.6737, -7.3944)
  arc A2 centre (0, 0) radius 26 clockwise from (25.3452, 5.7982) to (25.3452, -5.7982)
  circle C5 centre (31.4309, 31.4309) radius 2.159
  circle C6 centre (-31.4309, 31.4309) radius 2.159
  circle C7 centre (-0.2224, 0.034) radius 5.25
  circle C8 centre (31.4309, -31.4309) radius 2.159
  circle C9 centre (36.96, 18.76) radius 1.4
  circle C10 centre (18.76, 36.96) radius 1.4
  circle C11 centre (-18.76, 36.96) radius 1.4
  circle C12 centre (-36.96, 18.76) radius 1.4
  circle C13 centre (18.76, -36.96) radius 1.4
  arc A3 centre (-36.3855, 20.5361) radius 5.08 clockwise from (-41.4365, 21.0784) to (-41.1157, 22.3885)
  arc A4 centre (-28.9018, -28.9018) radius 12.5637 clockwise from (-28.9018, -41.4655) to (-41.4655, -28.9018)
  arc A5 centre (21.3665, -36.3855) radius 5.08 clockwise from (23.2139, -41.1177) to (21.9088, -41.4365)
  arc A6 centre (31.7692, -32.3242) radius 5.08 clockwise from (36.4994, -34.1766) to (33.6166, -37.0564)
  arc A7 centre (36.3855, -20.5361) radius 5.08 clockwise from (41.4655, -20.5361) to (41.1157, -22.3885)
  arc A8 centre (36.3855, 20.5361) radius 5.08 clockwise from (41.1157, 22.3885) to (41.4655, 20.5361)
  arc A9 centre (31.7692, 32.3242) radius 5.08 clockwise from (33.6166, 37.0564) to (36.4994, 34.1766)
  arc A10 centre (24.1231, 36.3855) radius 5.08 clockwise from (24.1231, 41.4655) to (26.5251, 40.8618)
  arc A11 centre (-24.1331, 36.3855) radius 5.08 clockwise from (-26.5185, 40.8706) to (-24.1331, 41.4655)
  arc A12 centre (-31.7692, 32.3242) radius 5.08 clockwise from (-36.4994, 34.1766) to (-34.1546, 36.8093)
hole "Hole1" HoleDepth 6 HoleDiameter 2.8 TipAngle 180
as_built_joint "As-built1"
position "Position1"
as_built_joint "As-built2"
as_built_joint "As-built9"
as_built_joint "As-built10" OffsetX 0 OffsetY 0 OffsetZ 0 AngleZ 0
position "Position2"
motion_link "MotionLink3" Value1 1000 Value2 100
motion_link "MotionLink4" Value1 1000 Value2 10000
position "Position3"
work_plane "WorkPlane1" AlongDistance 0 named "d28_1"
work_plane "WorkPlane2" AlongDistance 30 named "d78_1"
extrude "Extrude1" new body blind 2.5 named "d29_2"
sketch "Motor Spacers" plane through (0, 39, 0) normal (0, 1, 0) x axis (-1, 0, 0)
  line L1 (36.4994, 34.1766) -> (41.1157, 22.3885)
  line L2 (26.5185, 40.8706) -> (34.1546, 36.8093)
  line L3 (-24.1231, 41.4655) -> (24.1331, 41.4655)
  line L4 (-33.6166, 37.0564) -> (-26.5251, 40.8618)
  line L5 (-41.1157, 22.3885) -> (-36.4994, 34.1766)
  line L6 (-41.4655, -20.5361) -> (-41.4655, 20.5361)
  line L7 (-36.4994, -34.1766) -> (-41.1157, -22.3885)
  line L8 (-23.2139, -41.1177) -> (-33.6166, -37.0564)
  curve K1 (-21.3665, -41.4655) -> (-21.9088, -41.4365)
  line L9 (28.9018, -41.4655) -> (-21.3665, -41.4655)
  line L10 (41.4655, 20.5361) -> (41.4655, -28.9018)
  curve K2 (41.4365, 21.0784) -> (41.4655, 20.5361)
  line L11 (-28.1171, -18.8029) -> (-28.1171, -22.4983)
  line L12 (-21.1171, -22.4983) -> (-21.1171, -18.8029)
  line L13 (-21.1171, 8.8064) -> (-21.1171, 12.5017)
  line L14 (-28.1171, 12.5017) -> (-28.1171, 8.8064)
  line L15 (-2.2528, -17.5616) -> (-4.7199, -20.0288)
  line L16 (-9.6697, -15.0791) -> (-7.2025, -12.6119)
  line L17 (12.6119, 7.2025) -> (15.0791, 9.6697)
  line L18 (20.0288, 4.7199) -> (17.5616, 2.2528)
  line L19 (19.7207, 20.825) -> (23.4161, 20.825)
  line L20 (23.4161, 27.825) -> (19.7207, 27.825)
  line L21 (-7.8886, 27.825) -> (-11.5839, 27.825)
  line L22 (-11.5839, 20.825) -> (-7.8886, 20.825)
  circle C1 centre (36.96, 18.76) radius 1
  circle C2 centre (18.76, 36.96) radius 1
  circle C3 centre (-36.96, -18.76) radius 1
  circle C4 centre (-31.4309, -31.4309) radius 2.159
  circle C5 centre (31.4309, 31.4309) radius 2.159
  arc A1 centre (36.3855, 20.5361) radius 5.08 clockwise from (41.1157, 22.3885) to (41.4365, 21.0784)
  arc A2 centre (31.7692, 32.3242) radius 5.08 clockwise from (34.1546, 36.8093) to (36.4994, 34.1766)
  arc A3 centre (24.1331, 36.3855) radius 5.08 clockwise from (24.1331, 41.4655) to (26.5185, 40.8706)
  arc A4 centre (-24.1231, 36.3855) radius 5.08 clockwise from (-26.5251, 40.8618) to (-24.1231, 41.4655)
  arc A5 centre (-31.7692, 32.3242) radius 5.08 clockwise from (-36.4994, 34.1766) to (-33.6166, 37.0564)
  arc A6 centre (-36.3855, 20.5361) radius 5.08 clockwise from (-41.4655, 20.5361) to (-41.1157, 22.3885)
  arc A7 centre (-36.3855, -20.5361) radius 5.08 clockwise from (-41.1157, -22.3885) to (-41.4655, -20.5361)
  arc A8 centre (-31.7692, -32.3242) radius 5.08 clockwise from (-33.6166, -37.0564) to (-36.4994, -34.1766)
  arc A9 centre (-21.3665, -36.3855) radius 5.08 clockwise from (-21.9088, -41.4365) to (-23.2139, -41.1177)
  arc A10 centre (28.9018, -28.9018) radius 12.5637 clockwise from (41.4655, -28.9018) to (28.9018, -41.4655)
  arc A11 centre (-24.6171, -4.9983) radius 14.2414 clockwise from (-21.1171, -18.8029) to (-28.1171, -18.8029)
  arc A12 centre (-24.6171, -22.4983) radius 3.5 clockwise from (-21.1171, -22.4983) to (-28.1171, -22.4983)
  circle C6 centre (-24.6171, -22.4983) radius 2
  arc A13 centre (-24.6171, -4.9983) radius 14.2414 clockwise from (-28.1171, 8.8064) to (-21.1171, 8.8064)
  arc A14 centre (-24.6171, 12.5017) radius 3.5 clockwise from (-28.1171, 12.5017) to (-21.1171, 12.5017)
  circle C7 centre (-24.6171, 12.5017) radius 2
  arc A15 centre (5.1796, -5.1796) radius 14.4414 clockwise from (-2.2528, -17.5616) to (-7.2025, -12.6119)
  arc A16 centre (-7.1948, -17.5539) radius 3.5 clockwise from (-4.7199, -20.0288) to (-9.6697, -15.0791)
  circle C8 centre (-7.1948, -17.5539) radius 2
  arc A17 centre (5.1796, -5.1796) radius 14.4414 clockwise from (12.6119, 7.2025) to (17.5616, 2.2528)
  arc A18 centre (17.5539, 7.1948) radius 3.5 clockwise from (15.0791, 9.6697) to (20.0288, 4.7199)
  circle C9 centre (17.5539, 7.1948) radius 2
  arc A19 centre (5.9161, 24.325) radius 14.2414 clockwise from (19.7207, 27.825) to (19.7207, 20.825)
  arc A20 centre (23.4161, 24.325) radius 3.5 clockwise from (23.4161, 27.825) to (23.4161, 20.825)
  circle C10 centre (23.4161, 24.325) radius 2
  arc A21 centre (5.9161, 24.325) radius 14.2414 clockwise from (-7.8886, 20.825) to (-7.8886, 27.825)
  arc A22 centre (-11.5839, 24.325) radius 3.5 clockwise from (-11.5839, 20.825) to (-11.5839, 27.825)
  circle C11 centre (-11.5839, 24.325) radius 2
  circle C12 centre (-24.6171, -22.4983) radius 1.4
  circle C13 centre (-24.6171, 12.5017) radius 1.4
  circle C14 centre (-7.1948, -17.5539) radius 1.4
  circle C15 centre (17.5539, 7.1948) radius 1.4
  circle C16 centre (23.4161, 24.325) radius 1.4
  circle C17 centre (-11.5839, 24.325) radius 1.4
  circle C18 centre (-18.76, -36.96) radius 1
  circle C19 centre (0, 0) radius 5
  circle C20 centre (-31.4309, 31.4309) radius 2.159
  circle C21 centre (-36.96, 18.76) radius 1
  circle C22 centre (-18.76, 36.96) radius 1
  circle C23 centre (30.9023, -30.9023) radius 5.5
  point P68 (23.4161, 24.325)
  point P79 (23.4161, 24.325)
  concentric A12 C12
  concentric A14 C13
  concentric A16 C14
  concentric A18 C15
  coincident P68 P79
  concentric A22 C17
  equal C16 C17
  equal C15 C16
  equal C14 C15
  equal C12 C14
  equal C12 C13
  dimension "d76_1" diameter C13 = 2.8
sketch "Standoffs" plane through (0, 36.5, 0) normal (0, -1, 0) x axis (1, 0, 0)
  curve K1 (-41.4655, 20.5361) -> (-41.4365, 21.0784)
  line L1 (-41.4655, -28.9018) -> (-41.4655, 20.5361)
  line L2 (21.3665, -41.4655) -> (-28.9018, -41.4655)
  curve K2 (21.9088, -41.4365) -> (21.3665, -41.4655)
  line L3 (33.6166, -37.0564) -> (23.2139, -41.1177)
  line L4 (41.1157, -22.3885) -> (36.4994, -34.1766)
  line L5 (41.4655, 20.5361) -> (41.4655, -20.5361)
  line L6 (36.4994, 34.1766) -> (41.1157, 22.3885)
  line L7 (26.5251, 40.8618) -> (33.6166, 37.0564)
  line L8 (-24.1331, 41.4655) -> (24.1231, 41.4655)
  line L9 (-34.1546, 36.8093) -> (-26.5185, 40.8706)
  line L10 (-41.1157, 22.3885) -> (-36.4994, 34.1766)
  arc A1 centre (-36.3855, 20.5361) radius 5.08 clockwise from (-41.4365, 21.0784) to (-41.1157, 22.3885)
  arc A2 centre (-28.9018, -28.9018) radius 12.5637 clockwise from (-28.9018, -41.4655) to (-41.4655, -28.9018)
  arc A3 centre (21.3665, -36.3855) radius 5.08 clockwise from (23.2139, -41.1177) to (21.9088, -41.4365)
  arc A4 centre (31.7692, -32.3242) radius 5.08 clockwise from (36.4994, -34.1766) to (33.6166, -37.0564)
  arc A5 centre (36.3855, -20.5361) radius 5.08 clockwise from (41.4655, -20.5361) to (41.1157, -22.3885)
  arc A6 centre (36.3855, 20.5361) radius 5.08 clockwise from (41.1157, 22.3885) to (41.4655, 20.5361)
  arc A7 centre (31.7692, 32.3242) radius 5.08 clockwise from (33.6166, 37.0564) to (36.4994, 34.1766)
  arc A8 centre (24.1231, 36.3855) radius 5.08 clockwise from (24.1231, 41.4655) to (26.5251, 40.8618)
  arc A9 centre (-24.1331, 36.3855) radius 5.08 clockwise from (-26.5185, 40.8706) to (-24.1331, 41.4655)
  arc A10 centre (-31.7692, 32.3242) radius 5.08 clockwise from (-36.4994, 34.1766) to (-34.1546, 36.8093)
  circle C1 centre (18.76, -36.96) radius 1
  circle C2 centre (-31.4309, 31.4309) radius 2.159
  circle C3 centre (18.76, 36.96) radius 1
  circle C4 centre (-18.76, 36.96) radius 1
  circle C5 centre (31.4309, -31.4309) radius 2.159
  circle C6 centre (31.4309, 31.4309) radius 2.159
  circle C7 centre (-18.76, 36.96) radius 4.0817
  circle C8 centre (18.76, 36.96) radius 3.75
  circle C9 centre (36.96, 18.76) radius 3.75
  circle C10 centre (36.96, -18.76) radius 3.75
  circle C11 centre (18.76, -36.96) radius 3.75
  circle C12 centre (-37.3525, -16.6048) radius 3.75
  circle C13 centre (-17.3319, -36.9825) radius 3.75
  circle C14 centre (-37.3525, -16.6048) radius 1
  circle C15 centre (-17.3319, -36.9825) radius 1
  circle C16 centre (-36.96, 18.76) radius 1
  circle C17 centre (0, 0) radius 5
  circle C18 centre (36.96, -18.76) radius 1
  circle C19 centre (36.96, 18.76) radius 1
  circle C20 centre (-36.96, 18.76) radius 3.75
  point P42 (36.96, -18.76)
  point P53 (36.96, -18.76)
  point P41 (36.96, 18.76)
  point P54 (36.96, 18.76)
  point P1 (0, 0)
  point P44 (-37.3525, -16.6048)
  point P45 (-17.3319, -36.9825)
  concentric C4 C7
  concentric C3 C8
  concentric C1 C11
  equal C8 C9
  equal C9 C10
  equal C10 C11
  concentric C12 C14
  concentric C13 C15
  equal C14 C15
  equal C1 C14
  equal C11 C12
  coincident P42 P53
  coincident P41 P54
  concentric C16 C20
  equal C13 C20
  dimension "d182_1" diameter C8 = 7.5
  dimension "d282_1" distance P1 P44 = 16.6048 (= "18.6048175707 mm - 2 mm")
  dimension "d283_1" distance P1 P44 = 37.3525
  dimension "d284_1" distance P1 P45 = 17.3319 (= "19.3319078447 mm - 2 mm")
  dimension "d285_1" distance P1 P45 = 36.9825
extrude "Extrude11" add sketch "Standoffs" profile of C3 C8 C10 C13 C15 C16 C18 C20 to an object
